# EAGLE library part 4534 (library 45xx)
BCD COUNTER
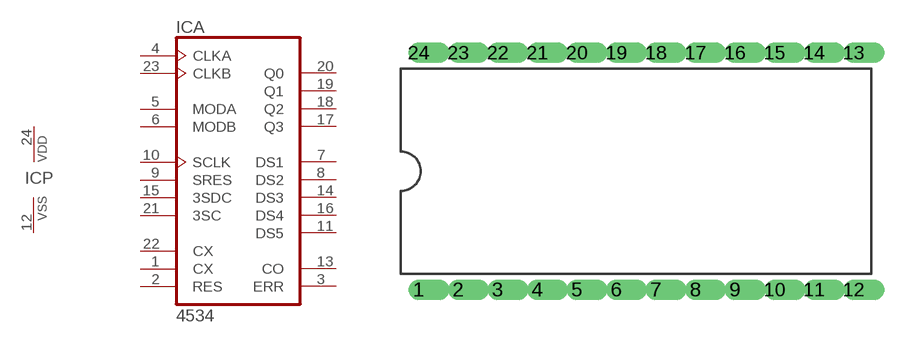
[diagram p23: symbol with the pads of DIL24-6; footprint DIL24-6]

Designator prefix IC; gates A=4534 P=PWRN

## 4534N  [DIL24-6]
1  A:CX  in
2  A:RES  in
3  A:ERR  out
4  A:CLKA  in
5  A:MODA  in
6  A:MODB  in
7  A:DS1  hiz
8  A:DS2  hiz
9  A:SRES  in
10  A:SCLK  in
11  A:DS5  hiz
12  P:VSS  pwr
13  A:CO  out
14  A:DS3  hiz
15  A:3SDC  in
16  A:DS4  hiz
17  A:Q3  hiz
18  A:Q2  hiz
19  A:Q1  hiz
20  A:Q0  hiz
21  A:3SC  in
22  A:CX  in
23  A:CLKB  in
24  P:VDD  pwr

## Footprint DIL24-6 (pad centres in mm)
Dual In Line 0.6 inch
drill 0.813 offset: 1 -13.97,-7.62; 2 -11.43,-7.62; 3 -8.89,-7.62; 4 -6.35,-7.62; 5 -3.81,-7.62; 6 -1.27,-7.62; 7 1.27,-7.62; 8 3.81,-7.62; 9 6.35,-7.62; 10 8.89,-7.62; 11 11.43,-7.62; 12 13.97,-7.62; 13 13.97,7.62; 14 11.43,7.62; 15 8.89,7.62; 16 6.35,7.62; 17 3.81,7.62; 18 1.27,7.62; 19 -1.27,7.62; 20 -3.81,7.62; 21 -6.35,7.62; 22 -8.89,7.62; 23 -11.43,7.62; 24 -13.97,7.62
